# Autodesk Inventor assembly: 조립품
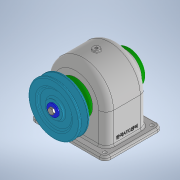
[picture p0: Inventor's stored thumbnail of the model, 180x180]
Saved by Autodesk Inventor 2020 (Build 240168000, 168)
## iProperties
Created: 2022-09
Part Number: 조립품
Document SubType Name: Assembly
Designer: Administrator
Author: Administrator
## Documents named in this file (16)
- C:\Users\Administrator\Desktop\720906V1017\조립품.iam
- C:\Users\Administrator\Desktop\720906V1017\본체.ipt
- C:\Users\Administrator\Desktop\720906V1017\축.ipt
- C:\Users\Administrator\Desktop\720906V1017\키 6 x 6 x 22.ipt
- C:\Users\Administrator\Desktop\720906V1017\스퍼기어.ipt
- C:\Users\Administrator\Desktop\720906V1017\칼라.ipt
- C:\Users\Administrator\Desktop\720906V1017\베어링 6203.ipt
- C:\Users\Administrator\Desktop\720906V1017\앞커버.ipt
- C:\Users\Administrator\Desktop\720906V1017\뒤커버.ipt
- C:\Users\Administrator\Desktop\720906V1017\오일 실 17 x 30 x 8.ipt
- C:\Users\Administrator\Desktop\720906V1017\볼트 M3 x 10.ipt
- C:\Users\Administrator\Desktop\720906V1017\키 5 x 5 x 18.ipt
- C:\Users\Administrator\Desktop\720906V1017\V-벨트풀리.ipt
- C:\Users\Administrator\Desktop\720906V1017\멈춤나사 M4 x 10.ipt
- C:\Users\Administrator\Desktop\720906V1017\와셔 6 x 22.ipt
- C:\Users\Administrator\Desktop\720906V1017\육각머리볼트 M3 x 8.ipt
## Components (9 placed, 2 different names)
1. V-벨트풀리:1
2. ISO 4762 M3 x 10:1
3. ISO 4762 M3 x 10:3
4. ISO 4762 M3 x 10:4
5. ISO 4762 M3 x 10:5
6. ISO 4762 M3 x 10:2
7. ISO 4762 M3 x 10:6
8. ISO 4762 M3 x 10:7
9. ISO 4762 M3 x 10:8
